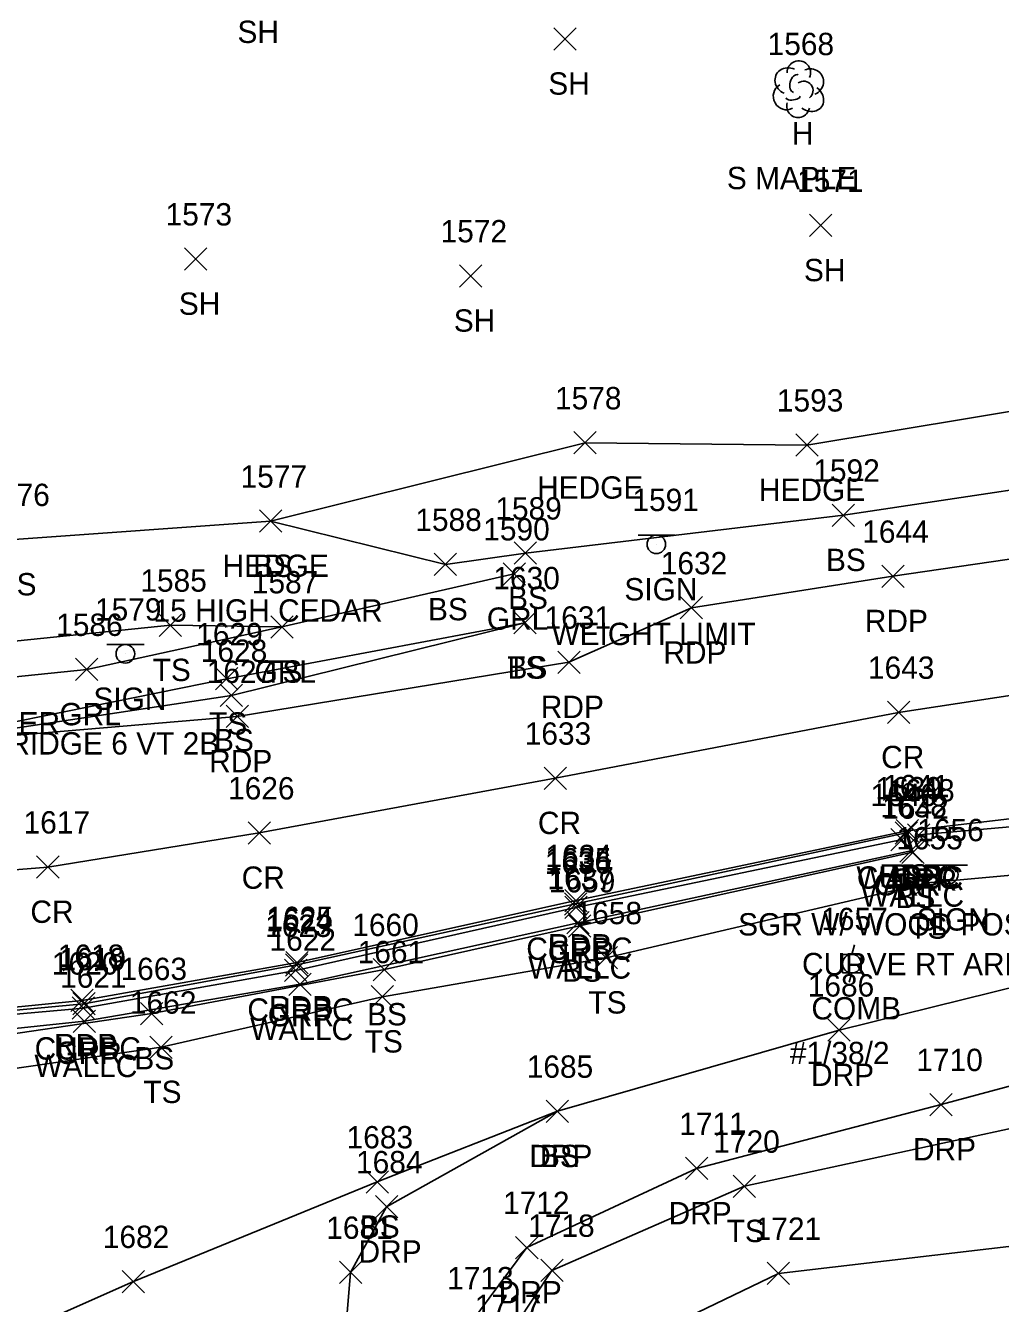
# Model space of a CAD drawing. Extents: x 1761340 to 1763889, y 696770 to 706023.
# Drawn here: x 1761761.6 to 1761848.8, y 700803.7 to 700918.1 of the extents above; entities that cross this region are included whole.
import ezdxf

# ---------------------------------------------------------------- set-up
doc = ezdxf.new("R2010")
doc.units = 0
for name, color, linetype in [('L_A', 7, 'Continuous'), ('L_C', 7, 'Continuous'), ('L_I', 7, 'Continuous'), ('L_TIC', 7, 'Continuous'), ('LAHR', 7, 'Continuous'), ('LAWA', 7, 'Continuous'), ('LELB', 7, 'Continuous'), ('LTD', 7, 'Continuous'), ('LW', 7, 'Continuous'), ('P_A', 7, 'Continuous'), ('P_I', 7, 'Continuous'), ('P_TIC', 7, 'Continuous'), ('PET', 7, 'Continuous'), ('PRC', 7, 'Continuous'), ('R_A', 7, 'Continuous'), ('R_C', 7, 'Continuous'), ('R_I', 7, 'Continuous'), ('R_TIC', 7, 'Continuous'), ('RC', 7, 'Continuous'), ('RDP', 7, 'Continuous'), ('RGR', 7, 'Continuous'), ('S_A', 7, 'Continuous'), ('S_C', 7, 'Continuous'), ('S_I', 7, 'Continuous'), ('SSGN', 7, 'Continuous'), ('U_A', 7, 'Continuous'), ('U_C', 7, 'Continuous'), ('U_I', 7, 'Continuous'), ('UP', 7, 'Continuous')]:
    doc.layers.add(name, color=color, linetype=linetype)

msp = doc.modelspace()

# ---------------------------------------------------------------- linework, layer by layer
at = {"layer": 'L_TIC'}
for points in [[(1761808.89, 700915.95), (1761810.89, 700917.95)], [(1761810.89, 700915.95), (1761808.89, 700917.95)], [(1761831.77, 700899.25), (1761833.77, 700901.25)], [(1761833.77, 700899.25), (1761831.77, 700901.25)], [(1761775.82, 700896.24), (1761777.82, 700898.24)], [(1761777.82, 700896.24), (1761775.82, 700898.24)], [(1761800.43, 700894.73), (1761802.43, 700896.73)], [(1761802.43, 700894.73), (1761800.43, 700896.73)], [(1761810.68, 700879.78), (1761812.68, 700881.78)], [(1761812.68, 700879.78), (1761810.68, 700881.78)], [(1761830.53, 700879.58), (1761832.53, 700881.58)], [(1761832.53, 700879.58), (1761830.53, 700881.58)], [(1761782.53, 700872.77), (1761784.53, 700874.77)], [(1761784.53, 700872.77), (1761782.53, 700874.77)], [(1761782.53, 700872.77), (1761784.53, 700874.77)], [(1761784.53, 700872.77), (1761782.53, 700874.77)], [(1761833.79, 700873.3), (1761835.79, 700875.3)], [(1761835.79, 700873.3), (1761833.79, 700875.3)], [(1761805.34, 700869.91), (1761807.34, 700871.91)], [(1761807.34, 700869.91), (1761805.34, 700871.91)], [(1761798.17, 700868.89), (1761800.17, 700870.89)], [(1761800.17, 700868.89), (1761798.17, 700870.89)], [(1761805.29, 700863.67), (1761807.29, 700865.67)], [(1761807.29, 700863.67), (1761805.29, 700865.67)], [(1761805.29, 700863.67), (1761807.29, 700865.67)], [(1761807.29, 700863.67), (1761805.29, 700865.67)], [(1761773.56, 700863.45), (1761775.56, 700865.45)], [(1761775.56, 700863.45), (1761773.56, 700865.45)], [(1761783.54, 700863.3), (1761785.54, 700865.3)], [(1761785.54, 700863.3), (1761783.54, 700865.3)], [(1761778.61, 700858.65), (1761780.61, 700860.65)], [(1761780.61, 700858.65), (1761778.61, 700860.65)], [(1761779.02, 700857.17), (1761781.02, 700859.17)], [(1761781.02, 700857.17), (1761779.02, 700859.17)], [(1761839.42, 700844.86), (1761841.42, 700846.86)], [(1761841.42, 700844.86), (1761839.42, 700846.86)], [(1761839.51, 700845.05), (1761841.51, 700847.05)], [(1761841.51, 700845.05), (1761839.51, 700847.05)], [(1761839.84, 700843.25), (1761841.84, 700845.25)], [(1761841.84, 700843.25), (1761839.84, 700845.25)], [(1761840.01, 700843.12), (1761842.01, 700845.12)], [(1761842.01, 700843.12), (1761840.01, 700845.12)], [(1761841.27, 700840.38), (1761843.27, 700842.38)], [(1761843.27, 700840.38), (1761841.27, 700842.38)], [(1761810.04, 700836.81), (1761812.04, 700838.81)], [(1761812.04, 700836.81), (1761810.04, 700838.81)], [(1761810.18, 700836.53), (1761812.18, 700838.53)], [(1761812.18, 700836.53), (1761810.18, 700838.53)], [(1761812.56, 700833.68), (1761814.56, 700835.68)], [(1761814.56, 700833.68), (1761812.56, 700835.68)], [(1761792.71, 700832.62), (1761794.71, 700834.62)], [(1761794.71, 700832.62), (1761792.71, 700834.62)], [(1761785.17, 700831.3), (1761787.17, 700833.3)], [(1761787.17, 700831.3), (1761785.17, 700833.3)], [(1761792.54, 700830.19), (1761794.54, 700832.19)], [(1761794.54, 700830.19), (1761792.54, 700832.19)], [(1761771.89, 700828.68), (1761773.89, 700830.68)], [(1761773.89, 700828.68), (1761771.89, 700830.68)], [(1761765.86, 700827.99), (1761767.86, 700829.99)], [(1761767.86, 700827.99), (1761765.86, 700829.99)], [(1761772.73, 700825.67), (1761774.73, 700827.67)], [(1761774.73, 700825.67), (1761772.73, 700827.67)], [(1761808.19, 700819.93), (1761810.19, 700821.93)], [(1761810.19, 700819.93), (1761808.19, 700821.93)], [(1761792.07, 700813.61), (1761794.07, 700815.61)], [(1761794.07, 700813.61), (1761792.07, 700815.61)], [(1761824.93, 700813.22), (1761826.93, 700815.22)], [(1761826.93, 700813.22), (1761824.93, 700815.22)], [(1761807.7, 700805.69), (1761809.7, 700807.69)], [(1761809.7, 700805.69), (1761807.7, 700807.69)], [(1761827.97, 700805.42), (1761829.97, 700807.42)], [(1761829.97, 700805.42), (1761827.97, 700807.42)], [(1761770.25, 700804.69), (1761772.25, 700806.69)], [(1761772.25, 700804.69), (1761770.25, 700806.69)]]:
    msp.add_lwpolyline(points, dxfattribs=at)
at = {"layer": 'LAHR'}
msp.add_lwpolyline([(1761783.53, 700873.77), (1761811.68, 700880.78), (1761831.53, 700880.58), (1761862.08, 700885.65)], dxfattribs=at)
at = {"layer": 'LAWA'}
msp.add_lwpolyline([(1761809.72, 700797.14), (1761828.97, 700806.42), (1761852.65, 700809.17), (1761873.57, 700806.1)], dxfattribs=at)
at = {"layer": 'LELB'}
for points in [[(1761723.72, 700872.01), (1761760.57, 700872.12), (1761783.53, 700873.77), (1761799.17, 700869.89), (1761806.34, 700870.91), (1761834.79, 700874.3), (1761863.42, 700878.6), (1761884.03, 700880.87), (1761911.52, 700884.53), (1761932.35, 700886.9), (1761937.16, 700891.64), (1761941.25, 700901.22)], [(1761730.98, 700860.35), (1761750.39, 700861.98), (1761774.56, 700864.45), (1761784.54, 700864.3)], [(1761754.88, 700854.64), (1761779.61, 700859.65), (1761806.29, 700864.67)], [(1761755.32, 700854.43), (1761780.02, 700858.17), (1761806.29, 700864.67)], [(1761886.34, 700848.25), (1761879.23, 700844.54), (1761857.13, 700842.74), (1761842.27, 700841.38), (1761813.56, 700834.68), (1761793.54, 700831.19), (1761773.73, 700826.67), (1761754.24, 700823.85), (1761739.4, 700821.55)], [(1761840.51, 700846.05), (1761841.01, 700844.12), (1761811.18, 700837.53), (1761793.71, 700833.62), (1761772.89, 700829.68), (1761754.58, 700827), (1761740.08, 700825.94), (1761728.96, 700825.89), (1761725.15, 700825.85)], [(1761805.48, 700793.43), (1761803.94, 700799.51), (1761808.7, 700806.69), (1761825.93, 700814.22), (1761855.12, 700820.55), (1761878.34, 700823.71)], [(1761687.21, 700769.13), (1761700.84, 700775.67), (1761725.83, 700785.51), (1761771.25, 700805.69), (1761793.07, 700814.61), (1761809.19, 700820.93)]]:
    msp.add_lwpolyline(points, dxfattribs=at)
at = {"layer": 'LTD'}
msp.add_line((1761830.75, 700912.49), (1761830.75, 700912.49), dxfattribs=at)
msp.add_line((1761830.75, 700912.49), (1761830.75, 700912.49), dxfattribs=at)
msp.add_arc((1761830.8, 700913.93), 1.05, 335.5272, 180.9563, dxfattribs=at)
for centre, major_axis, ratio, start_param, end_param in [((1761829.96, 700913.16), (1.21, -0.51), 0.895232, 1.570796, 4.712389), ((1761830.54, 700912.95), (-0.208, -0.792), 0.645439, 3.141593, 6.283185), ((1761831.79, 700913.08), (-1.14, -0.48), 0.949671, 1.570796, 4.712389), ((1761829.67, 700911.78), (0.58, -1.04), 0.959034, 3.141593, 6.283185), ((1761831.25, 700912.33), (-0.5, 0.667), 0.989748, 3.141593, 6.283185), ((1761831.75, 700911.66), (-1.09, 0.79), 0.841452, 1.570796, 4.712389), ((1761830.29, 700911.74), (-0.625, -0.083), 0.423636, 0, 3.141593), ((1761830.75, 700910.99), (0.26, 1.06), 0.942809, 1.570796, 4.712389)]:
    msp.add_ellipse(centre, major_axis=major_axis, ratio=ratio, start_param=start_param, end_param=end_param, dxfattribs=at)
at = {"layer": 'LW'}
msp.add_lwpolyline([(1761725.21, 700826.3), (1761741.43, 700826.32), (1761766.86, 700828.99), (1761786.17, 700832.3), (1761811.04, 700837.81), (1761840.84, 700844.25), (1761840.42, 700845.86)], dxfattribs=at)
at = {"layer": 'P_TIC'}
for points in [[(1761838.22, 700867.83), (1761840.22, 700869.83)], [(1761840.22, 700867.83), (1761838.22, 700869.83)], [(1761820.19, 700865.01), (1761822.19, 700867.01)], [(1761822.19, 700865.01), (1761820.19, 700867.01)], [(1761809.22, 700860.14), (1761811.22, 700862.14)], [(1761811.22, 700860.14), (1761809.22, 700862.14)], [(1761838.73, 700855.65), (1761840.73, 700857.65)], [(1761840.73, 700855.65), (1761838.73, 700857.65)], [(1761779.55, 700855.28), (1761781.55, 700857.28)], [(1761781.55, 700855.28), (1761779.55, 700857.28)], [(1761808.01, 700849.75), (1761810.01, 700851.75)], [(1761810.01, 700849.75), (1761808.01, 700851.75)], [(1761781.51, 700844.85), (1761783.51, 700846.85)], [(1761783.51, 700844.85), (1761781.51, 700846.85)], [(1761839.51, 700845.05), (1761841.51, 700847.05)], [(1761841.51, 700845.05), (1761839.51, 700847.05)], [(1761762.59, 700841.8), (1761764.59, 700843.8)], [(1761764.59, 700841.8), (1761762.59, 700843.8)], [(1761809.86, 700838.79), (1761811.86, 700840.79)], [(1761811.86, 700838.79), (1761809.86, 700840.79)], [(1761784.9, 700833.25), (1761786.9, 700835.25)], [(1761786.9, 700833.25), (1761784.9, 700835.25)], [(1761765.65, 700829.86), (1761767.65, 700831.86)], [(1761767.65, 700829.86), (1761765.65, 700831.86)]]:
    msp.add_lwpolyline(points, dxfattribs=at)
at = {"layer": 'PET'}
for points in [[(1761729.33, 700852.74), (1761740.9, 700853.18), (1761754.83, 700854.09), (1761780.55, 700856.28), (1761810.22, 700861.14), (1761821.19, 700866.01), (1761839.22, 700868.83), (1761861.11, 700872.05), (1761884.87, 700875.71), (1761913.75, 700879.27), (1761932.44, 700880.62), (1761962.06, 700884.59), (1761979.87, 700885.62), (1762011.62, 700885.45), (1762036.8, 700884.84)], [(1761729.33, 700852.74), (1761727.43, 700840.67), (1761725.47, 700828.38), (1761741.06, 700828.32), (1761766.65, 700830.86), (1761785.9, 700834.25), (1761810.86, 700839.79), (1761840.51, 700846.05), (1761863.89, 700848.79), (1761886.86, 700850.87), (1761909.09, 700853.95), (1761931.55, 700856.46), (1761961.83, 700859.61), (1761986.64, 700861.18), (1762018.61, 700861.2), (1762035.74, 700860.87)]]:
    msp.add_lwpolyline(points, dxfattribs=at)
at = {"layer": 'PRC'}
msp.add_lwpolyline([(1761727.43, 700840.67), (1761741.7, 700841.02), (1761763.59, 700842.8), (1761782.51, 700845.85), (1761809.01, 700850.75), (1761839.73, 700856.65), (1761862.6, 700860.14), (1761886.29, 700863.33), (1761916.3, 700867.26), (1761941.01, 700869.9), (1761962.56, 700871.62), (1761986.3, 700872.71), (1762008.01, 700873.29), (1762036.15, 700873.12)], dxfattribs=at)
at = {"layer": 'R_TIC'}
for points in [[(1761804.33, 700868.04), (1761806.33, 700870.04)], [(1761806.33, 700868.04), (1761804.33, 700870.04)], [(1761783.54, 700863.3), (1761785.54, 700865.3)], [(1761785.54, 700863.3), (1761783.54, 700865.3)], [(1761766.08, 700859.49), (1761768.08, 700861.49)], [(1761768.08, 700859.49), (1761766.08, 700861.49)], [(1761839.05, 700844.25), (1761841.05, 700846.25)], [(1761841.05, 700844.25), (1761839.05, 700846.25)], [(1761839.42, 700844.86), (1761841.42, 700846.86)], [(1761841.42, 700844.86), (1761839.42, 700846.86)], [(1761840.54, 700844.67), (1761842.54, 700846.67)], [(1761842.54, 700844.67), (1761840.54, 700846.67)], [(1761809.83, 700838.49), (1761811.83, 700840.49)], [(1761811.83, 700838.49), (1761809.83, 700840.49)], [(1761809.85, 700838.19), (1761811.85, 700840.19)], [(1761811.85, 700838.19), (1761809.85, 700840.19)], [(1761784.87, 700833.04), (1761786.87, 700835.04)], [(1761786.87, 700833.04), (1761784.87, 700835.04)], [(1761784.78, 700832.54), (1761786.78, 700834.54)], [(1761786.78, 700832.54), (1761784.78, 700834.54)], [(1761765.82, 700829.56), (1761767.82, 700831.56)], [(1761767.82, 700829.56), (1761765.82, 700831.56)], [(1761765.78, 700829.17), (1761767.78, 700831.17)], [(1761767.78, 700829.17), (1761765.78, 700831.17)], [(1761833.4, 700827.2), (1761835.4, 700829.2)], [(1761835.4, 700827.2), (1761833.4, 700829.2)], [(1761842.53, 700820.53), (1761844.53, 700822.53)], [(1761844.53, 700820.53), (1761842.53, 700822.53)], [(1761808.19, 700819.93), (1761810.19, 700821.93)], [(1761810.19, 700819.93), (1761808.19, 700821.93)], [(1761820.66, 700814.81), (1761822.66, 700816.81)], [(1761822.66, 700814.81), (1761820.66, 700816.81)], [(1761792.91, 700811.38), (1761794.91, 700813.38)], [(1761794.91, 700811.38), (1761792.91, 700813.38)], [(1761805.46, 700807.73), (1761807.46, 700809.73)], [(1761807.46, 700807.73), (1761805.46, 700809.73)], [(1761789.69, 700805.51), (1761791.69, 700807.51)], [(1761791.69, 700805.51), (1761789.69, 700807.51)]]:
    msp.add_lwpolyline(points, dxfattribs=at)
at = {"layer": 'RC'}
msp.add_lwpolyline([(1761725.38, 700828.02), (1761740.98, 700828.12), (1761766.82, 700830.56), (1761785.87, 700834.04), (1761810.83, 700839.49), (1761840.42, 700845.86)], dxfattribs=at)
at = {"layer": 'RDP'}
for points in [[(1761909.75, 700852.01), (1761910.06, 700848.6), (1761904.32, 700847.79), (1761900.72, 700845.11), (1761895.97, 700834.47), (1761888.06, 700828.96), (1761879.46, 700828.71), (1761868.22, 700828.16), (1761843.53, 700821.53), (1761821.66, 700815.81), (1761806.46, 700808.73), (1761801.46, 700801.99), (1761799.74, 700797.31), (1761801.84, 700789.96)], [(1761792.74, 700783.52), (1761789.8, 700796.06), (1761790.69, 700806.51), (1761793.91, 700812.38), (1761809.19, 700820.93), (1761834.4, 700828.2), (1761856.49, 700833.67), (1761872.42, 700837.86), (1761886.1, 700844.23), (1761888.88, 700847.64), (1761886.86, 700850.87)]]:
    msp.add_lwpolyline(points, dxfattribs=at)
at = {"layer": 'RGR'}
for points in [[(1761730.58, 700857.75), (1761750.49, 700858.78), (1761767.08, 700860.49), (1761784.54, 700864.3), (1761805.33, 700869.04)], [(1761841.54, 700845.67), (1761853.45, 700846.72), (1761866.76, 700846.98), (1761879.49, 700846.3)], [(1761725.26, 700827.74), (1761740.93, 700827.87), (1761766.78, 700830.17), (1761785.78, 700833.54), (1761810.85, 700839.19), (1761840.05, 700845.25)]]:
    msp.add_lwpolyline(points, dxfattribs=at)
at = {"layer": 'SSGN'}
for p, q in [((1761816.41, 700872.52), (1761819.74, 700872.52)), ((1761818.05, 700871.69), (1761818.05, 700871.69)), ((1761768.88, 700862.72), (1761772.22, 700862.72)), ((1761770.53, 700861.89), (1761770.53, 700861.89)), ((1761842.57, 700842.97), (1761845.9, 700842.97)), ((1761844.22, 700842.13), (1761844.22, 700842.13))]:
    msp.add_line(p, q, dxfattribs=at)
for centre in [(1761818.05, 700871.69), (1761770.53, 700861.89), (1761844.22, 700842.13)]:
    msp.add_circle(centre, 0.833, dxfattribs=at)
at = {"layer": 'UP'}
for p, q in [((1761834.71, 700833.32), (1761834.71, 700834.98)), ((1761834.71, 700834.98), (1761836.38, 700834.98)), ((1761835.8, 700835.82), (1761835.55, 700834.98)), ((1761836.38, 700834.98), (1761836.38, 700833.32)), ((1761835.55, 700834.15), (1761835.55, 700834.15)), ((1761836.38, 700833.32), (1761834.71, 700833.32)), ((1761835.3, 700832.48), (1761835.55, 700833.32))]:
    msp.add_line(p, q, dxfattribs=at)
msp.add_circle((1761835.55, 700834.15), 0.833, dxfattribs=at)

# ---------------------------------------------------------------- texts
at = {"layer": 'L_A'}
for s, p in [('SH', (1761780.56, 700916.58)), ('SH', (1761808.38, 700911.95)), ('H', (1761830.18, 700907.49)), ('SH', (1761831.26, 700895.25)), ('SH', (1761775.31, 700892.24)), ('SH', (1761799.92, 700890.73)), ('HEDGE', (1761807.38, 700875.78)), ('HEDGE', (1761827.23, 700875.58)), ('BS', (1761833.23, 700869.3)), ('HEDGE', (1761779.23, 700868.77)), ('BS', (1761781.97, 700868.77)), ('BS', (1761759.01, 700867.12)), ('BS', (1761804.78, 700865.91)), ('BS', (1761797.61, 700864.89)), ('TS', (1761772.97, 700859.45)), ('TS', (1761782.95, 700859.3)), ('TS', (1761804.7, 700859.67)), ('BS', (1761804.73, 700859.67)), ('TS', (1761778.02, 700854.65)), ('BS', (1761778.46, 700853.17)), ('WALLC', (1761835.96, 700840.86)), ('BS', (1761838.95, 700841.05)), ('WALLC', (1761836.38, 700839.25)), ('BS', (1761839.45, 700839.12)), ('TS', (1761840.68, 700836.38)), ('WALLC', (1761806.58, 700832.81)), ('BS', (1761809.62, 700832.53)), ('TS', (1761811.97, 700829.68)), ('BS', (1761792.16, 700828.62)), ('WALLC', (1761781.7, 700827.3)), ('TS', (1761791.95, 700826.19)), ('BS', (1761771.33, 700824.68)), ('WALLC', (1761762.39, 700823.99)), ('TS', (1761772.14, 700821.67)), ('BS', (1761807.63, 700815.93)), ('BS', (1761791.51, 700809.61)), ('TS', (1761824.34, 700809.22))]:
    msp.add_text(s, height=2, dxfattribs=at).set_placement(p)
at = {"layer": 'L_C'}
for s, p in [('S MAPLE', (1761824.36, 700903.49)), ('15 HIGH CEDAR', (1761773.05, 700864.77)), ('M BOXELDER', (1761747.15, 700854.67))]:
    msp.add_text(s, height=2, dxfattribs=at).set_placement(p)
at = {"layer": 'L_I'}
for s, p in [('1568', (1761828.01, 700915.49)), ('1571', (1761830.65, 700903.25)), ('1573', (1761774.13, 700900.24)), ('1572', (1761798.74, 700898.73)), ('1578', (1761808.98, 700883.78)), ('1593', (1761828.84, 700883.58)), ('1592', (1761832.1, 700877.3)), ('1577', (1761780.84, 700876.77)), ('1577', (1761780.84, 700876.77)), ('1576', (1761757.82, 700875.12)), ('1589', (1761803.64, 700873.91)), ('1588', (1761796.48, 700872.89)), ('1585', (1761771.87, 700867.45)), ('1587', (1761781.85, 700867.3)), ('1630', (1761803.46, 700867.67)), ('1630', (1761803.46, 700867.67)), ('1629', (1761776.87, 700862.65)), ('1628', (1761777.28, 700861.17)), ('1639', (1761837.67, 700848.86)), ('1641', (1761838.34, 700849.05)), ('1638', (1761838.1, 700847.25)), ('1642', (1761838.27, 700847.12)), ('1655', (1761839.53, 700844.38)), ('1637', (1761808.3, 700840.81)), ('1659', (1761808.43, 700840.53)), ('1658', (1761810.82, 700837.68)), ('1660', (1761790.84, 700836.62)), ('1622', (1761783.43, 700835.3)), ('1661', (1761791.32, 700834.19)), ('1663', (1761770.1, 700832.68)), ('1621', (1761764.69, 700831.99)), ('1662', (1761770.94, 700829.67)), ('1685', (1761806.45, 700823.93)), ('1683', (1761790.33, 700817.61)), ('1720', (1761823.15, 700817.22)), ('1682', (1761768.51, 700808.69)), ('1718', (1761806.58, 700809.69)), ('1721', (1761826.85, 700809.42)), ('1717', (1761801.81, 700802.51))]:
    msp.add_text(s, height=2, dxfattribs=at).set_placement(p)
at = {"layer": 'P_A'}
for s, p in [('RDP', (1761836.71, 700863.83)), ('RDP', (1761818.68, 700861.01)), ('RDP', (1761807.71, 700856.14)), ('RDP', (1761778.03, 700851.28)), ('CR', (1761838.17, 700851.65)), ('CR', (1761807.45, 700845.75)), ('CR', (1761780.94, 700840.85)), ('RDP', (1761838, 700841.05)), ('CR', (1761762.03, 700837.8)), ('RDP', (1761808.35, 700834.79)), ('RDP', (1761783.38, 700829.25)), ('RDP', (1761764.14, 700825.86))]:
    msp.add_text(s, height=2, dxfattribs=at).set_placement(p)
at = {"layer": 'P_I'}
for s, p in [('1644', (1761836.48, 700871.83)), ('1632', (1761818.45, 700869.01)), ('1631', (1761808.05, 700864.14)), ('1627', (1761777.81, 700859.28)), ('1643', (1761836.99, 700859.65)), ('1633', (1761806.27, 700853.75)), ('1626', (1761779.72, 700848.85)), ('1641', (1761838.34, 700849.05)), ('1617', (1761761.42, 700845.8)), ('1634', (1761808.12, 700842.79)), ('1625', (1761783.16, 700837.25)), ('1618', (1761764.48, 700833.86))]:
    msp.add_text(s, height=2, dxfattribs=at).set_placement(p)
at = {"layer": 'R_A'}
for s, p in [('GRL', (1761802.88, 700864.04)), ('GRL', (1761782.09, 700859.3)), ('GRL', (1761764.63, 700855.49)), ('CURBC', (1761836, 700840.86)), ('GRR', (1761839.03, 700840.67)), ('GRR', (1761837.53, 700840.25)), ('CURBC', (1761806.41, 700834.49)), ('GRR', (1761808.34, 700834.19)), ('CURBC', (1761781.45, 700829.04)), ('GRR', (1761783.27, 700828.54)), ('CURBC', (1761762.41, 700825.56)), ('GRR', (1761764.27, 700825.17)), ('DRP', (1761831.89, 700823.2)), ('DRP', (1761806.68, 700815.93)), ('DRP', (1761841.02, 700816.53)), ('DRP', (1761819.15, 700810.81)), ('DRP', (1761791.4, 700807.38)), ('DRP', (1761803.94, 700803.73))]:
    msp.add_text(s, height=2, dxfattribs=at).set_placement(p)
at = {"layer": 'R_C'}
msp.add_text('SGR W/ WOOD POSTS', height=2, dxfattribs=at).set_placement((1761825.37, 700836.67))
at = {"layer": 'R_I'}
for s, p in [('1590', (1761802.56, 700872.04)), ('1587', (1761781.85, 700867.3)), ('1586', (1761764.34, 700863.49)), ('1639', (1761837.67, 700848.86)), ('1648', (1761838.8, 700848.67)), ('1640', (1761837.22, 700848.25)), ('1636', (1761808.06, 700842.19)), ('1635', (1761808.09, 700842.49)), ('1623', (1761783.04, 700836.54)), ('1624', (1761783.13, 700837.04)), ('1620', (1761763.95, 700833.17)), ('1619', (1761764.64, 700833.56)), ('1686', (1761831.6, 700831.2)), ('1685', (1761806.45, 700823.93)), ('1710', (1761841.32, 700824.53)), ('1711', (1761820.1, 700818.81)), ('1684', (1761791.17, 700815.38)), ('1712', (1761804.33, 700811.73)), ('1681', (1761788.51, 700809.51)), ('1713', (1761799.33, 700804.99))]:
    msp.add_text(s, height=2, dxfattribs=at).set_placement(p)
at = {"layer": 'S_A'}
for p in [(1761815.19, 700866.67), (1761767.67, 700856.87), (1761841.35, 700837.11)]:
    msp.add_text('SIGN', height=2, dxfattribs=at).set_placement(p)
at = {"layer": 'S_C'}
for s, p in [('WEIGHT LIMIT', (1761808.66, 700862.67)), ('BRIDGE 6 VT 2B', (1761758.27, 700852.87)), ('CURVE RT ARROW', (1761831.09, 700833.11))]:
    msp.add_text(s, height=2, dxfattribs=at).set_placement(p)
at = {"layer": 'S_I'}
for s, p in [('1591', (1761815.91, 700874.67)), ('1579', (1761767.81, 700864.87)), ('1656', (1761841.4, 700845.11))]:
    msp.add_text(s, height=2, dxfattribs=at).set_placement(p)
at = {"layer": 'U_A'}
msp.add_text('COMB', height=2, dxfattribs=at).set_placement((1761831.93, 700829.15))
at = {"layer": 'U_C'}
msp.add_text('#1/38/2', height=2, dxfattribs=at).set_placement((1761830, 700825.15))
at = {"layer": 'U_I'}
msp.add_text('1657', height=2, dxfattribs=at).set_placement((1761832.81, 700837.15))

doc.saveas('drawing.dxf')
